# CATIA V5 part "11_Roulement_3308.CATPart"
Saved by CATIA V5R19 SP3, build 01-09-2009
Part number: 11_Roulement_3308
Definition: 11_Roulement_3308
Bounding box of the stored display mesh (mm): x 0 to 36.5, y -45 to 45, z -45 to 45
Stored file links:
  C:\Users\Frédéric\Documents\WF\STSCPI 09-11\Projets\Projet multiplicateur eolienne\Maquette eolienne\Standard\11_Roulement_3308.CATPart
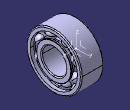
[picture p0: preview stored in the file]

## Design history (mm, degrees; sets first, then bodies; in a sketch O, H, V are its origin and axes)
AxisSystem1: origin (0, 0, 0), X (1, 0, 0), Y (0, 1, 0), Z (0, 0, 1)
Body1 "1" (main body)
  Solid1: solid without history
Body2 "2"
  Solid2: solid without history
Body3 "3"
  Solid3: solid without history
Body4 "4"
  Solid4: solid without history
Body5 "5"
  Solid5: solid without history
Body6 "6"
  Solid6: solid without history
Body7 "7"
  Solid7: solid without history
Body8 "8"
  Solid8: solid without history
Body9 "9"
  Solid9: solid without history
Body10 "10"
  Solid10: solid without history
Body11 "11"
  Solid11: solid without history
Body12 "12"
  Solid12: solid without history
Body13 "13"
  Solid13: solid without history
Body14 "14"
  Solid14: solid without history
Body15 "15"
  Solid15: solid without history
Body16 "16"
  Solid16: solid without history
Body17 "17"
  Solid17: solid without history
Body18 "18"
  Solid18: solid without history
